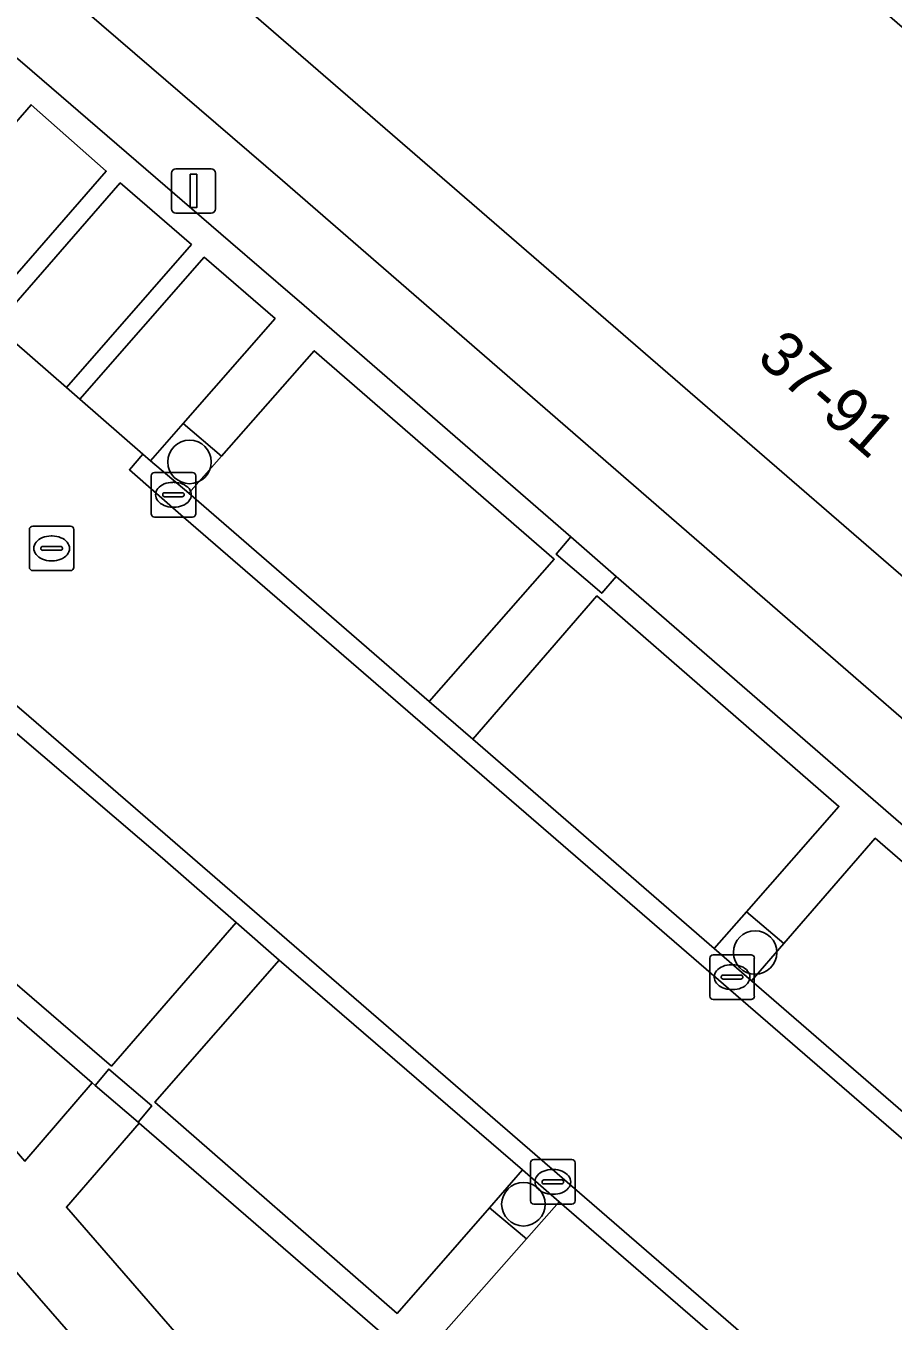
# Model space of a CAD drawing. Extents: x 161881 to 162523, y 381678 to 382381.
# Drawn here: x 162001.95 to 162021.44, y 382171.7 to 382200.83 of the extents above; entities that cross this region are included whole.
import ezdxf

# ---------------------------------------------------------------- set-up
doc = ezdxf.new("R2010")
doc.units = 0
for name, color, linetype in [('IMGEO_Boom', 7, 'Continuous'), ('IMGEO_Erf', 7, 'Continuous'), ('IMGEO_Groenvoorziening', 7, 'Continuous'), ('IMGEO_Kolk', 7, 'Continuous'), ('IMGEO_Lichtmast', 7, 'Continuous'), ('IMGEO_Pand', 7, 'Continuous'), ('IMGEO_Pand_nummerreeks', 7, 'Continuous'), ('IMGEO_Parkeervlak_open', 7, 'Continuous'), ('IMGEO_Rijbaan_lokaal_open', 7, 'Continuous'), ('IMGEO_Rioolput', 7, 'Continuous'), ('IMGEO_Voetpad_op_trap', 7, 'Continuous'), ('IMGEO_Voetpad_open', 7, 'Continuous')]:
    doc.layers.add(name, color=color, linetype=linetype)

msp = doc.modelspace()

# ---------------------------------------------------------------- linework, layer by layer
at = {"layer": 'IMGEO_Boom'}
for centre in [(162005.625, 382191.022), (162018.336, 382179.992), (162013.128, 382174.328)]:
    msp.add_circle(centre, 0.489, dxfattribs=at)
at = {"layer": 'IMGEO_Erf'}
for points in [[(162041.152, 382183.891), (162035.04, 382176.852), (162004.335, 382203.455), (162003.926, 382202.983), (162003.275, 382203.547), (162002.15, 382202.152), (162007.715, 382197.353), (162034.901, 382173.742), (162058.69, 382153.142)], [(162030.201, 382140.112), (161996.66, 382178.627), (161990.016, 382186.254), (161988.587, 382187.894), (161980.177, 382180.625), (161980.188, 382180.574), (161984.998, 382159.715), (161990.302, 382150.73)]]:
    msp.add_lwpolyline(points, dxfattribs=at)
at = {"layer": 'IMGEO_Groenvoorziening'}
for points in [[(162006.341, 382191.151), (162005.484, 382191.889), (162004.744, 382191.044), (162005.61, 382190.321)], [(161997.32, 382182.356), (161993.312, 382185.812), (161993.031, 382185.565), (162001.926, 382175.294), (162003.438, 382177.057)], [(162018.145, 382180.908), (162017.419, 382180.08), (162018.255, 382179.355), (162018.982, 382180.193)], [(162004.491, 382176.151), (162002.856, 382174.263), (162013.07, 382162.502), (162016.152, 382166.051)], [(162013.934, 382174.385), (162013.107, 382175.099), (162012.366, 382174.25), (162013.2, 382173.552)]]:
    msp.add_lwpolyline(points, close=True, dxfattribs=at)
at = {"layer": 'IMGEO_Kolk'}
for p, q in [((162004.763, 382189.858), (162004.763, 382190.71)), ((162004.838, 382190.784), (162005.69, 382190.784)), ((162005.764, 382190.71), (162005.764, 382189.858)), ((162005.251, 382190.564), (162005.276, 382190.564)), ((162005.022, 382190.278), (162005.022, 382190.29)), ((162005.46, 382190.241), (162005.062, 382190.241)), ((162005.065, 382190.327), (162005.463, 382190.327)), ((162005.506, 382190.29), (162005.506, 382190.278)), ((162005.274, 382190.004), (162005.249, 382190.004)), ((162005.69, 382189.784), (162004.838, 382189.784)), ((162017.392, 382179.936), (162018.244, 382179.936)), ((162017.317, 382179.01), (162017.317, 382179.862)), ((162017.805, 382179.716), (162017.83, 382179.716)), ((162018.318, 382179.862), (162018.318, 382179.01)), ((162017.576, 382179.43), (162017.576, 382179.442)), ((162018.014, 382179.393), (162017.616, 382179.393)), ((162017.619, 382179.479), (162018.017, 382179.479)), ((162018.06, 382179.442), (162018.06, 382179.43)), ((162017.828, 382179.156), (162017.803, 382179.156)), ((162018.244, 382178.936), (162017.392, 382178.936)), ((162013.289, 382174.406), (162013.289, 382175.258)), ((162013.364, 382175.332), (162014.216, 382175.332)), ((162014.29, 382175.258), (162014.29, 382174.406)), ((162013.777, 382175.112), (162013.802, 382175.112)), ((162013.548, 382174.826), (162013.548, 382174.838)), ((162013.986, 382174.789), (162013.588, 382174.789)), ((162013.591, 382174.875), (162013.989, 382174.875)), ((162014.032, 382174.838), (162014.032, 382174.826)), ((162013.8, 382174.552), (162013.775, 382174.552)), ((162014.216, 382174.332), (162013.364, 382174.332))]:
    msp.add_line(p, q, dxfattribs=at)
for points in [[(162004.763, 382189.858), (162004.763, 382190.71)], [(162004.838, 382190.784), (162005.69, 382190.784)], [(162005.764, 382190.71), (162005.764, 382189.858)], [(162005.69, 382189.784), (162004.838, 382189.784)], [(162017.392, 382179.936), (162018.244, 382179.936)], [(162017.317, 382179.01), (162017.317, 382179.862)], [(162018.318, 382179.862), (162018.318, 382179.01)], [(162018.244, 382178.936), (162017.392, 382178.936)], [(162013.289, 382174.406), (162013.289, 382175.258)], [(162013.364, 382175.332), (162014.216, 382175.332)], [(162014.29, 382175.258), (162014.29, 382174.406)], [(162014.216, 382174.332), (162013.364, 382174.332)]]:
    msp.add_lwpolyline(points, dxfattribs=at)
for centre, radius, start, end in [((162004.84, 382190.708), 0.0765, 91.552, 178.448), ((162004.84, 382190.708), 0.0765, 91.552, 178.448), ((162005.688, 382190.708), 0.0765, 1.552, 88.448), ((162005.688, 382190.708), 0.0765, 1.552, 88.448), ((162005.062, 382190.287), 0.0403, 85.8775, 175.7526), ((162005.059, 382190.277), 0.0366, 178.938, 274.7102), ((162005.463, 382190.284), 0.043, 264.8664, 352.4533), ((162005.467, 382190.289), 0.0386, 1.7309, 96.639), ((162004.84, 382189.86), 0.0765, 181.552, 268.448), ((162004.84, 382189.86), 0.0765, 181.552, 268.448), ((162005.688, 382189.86), 0.0765, 271.552, 358.448), ((162005.688, 382189.86), 0.0765, 271.552, 358.448), ((162017.394, 382179.86), 0.0765, 91.552, 178.448), ((162017.394, 382179.86), 0.0765, 91.552, 178.448), ((162018.242, 382179.86), 0.0765, 1.552, 88.448), ((162018.242, 382179.86), 0.0765, 1.552, 88.448), ((162017.616, 382179.439), 0.0403, 85.8775, 175.7526), ((162017.613, 382179.429), 0.0366, 178.938, 274.7102), ((162018.017, 382179.436), 0.043, 264.8664, 352.4533), ((162018.021, 382179.441), 0.0386, 1.7309, 96.639), ((162017.394, 382179.012), 0.0765, 181.552, 268.448), ((162017.394, 382179.012), 0.0765, 181.552, 268.448), ((162018.242, 382179.012), 0.0765, 271.552, 358.448), ((162018.242, 382179.012), 0.0765, 271.552, 358.448), ((162013.366, 382175.256), 0.0765, 91.552, 178.448), ((162013.366, 382175.256), 0.0765, 91.552, 178.448), ((162014.214, 382175.256), 0.0765, 1.552, 88.448), ((162014.214, 382175.256), 0.0765, 1.552, 88.448), ((162013.588, 382174.835), 0.0403, 85.8775, 175.7526), ((162013.585, 382174.825), 0.0366, 178.938, 274.7102), ((162013.989, 382174.832), 0.043, 264.8664, 352.4533), ((162013.993, 382174.837), 0.0386, 1.7309, 96.639), ((162013.366, 382174.408), 0.0765, 181.552, 268.448), ((162013.366, 382174.408), 0.0765, 181.552, 268.448), ((162014.214, 382174.408), 0.0765, 271.552, 358.448), ((162014.214, 382174.408), 0.0765, 271.552, 358.448)]:
    msp.add_arc(centre, radius, start, end, dxfattribs=at)
for centre, major_axis, ratio, start_param, end_param in [((162005.25, 382190.284), (-0.387, 0.002), 0.722429, 4.712389, 7.853982), ((162005.275, 382190.284), (-0.39, 0.002), 0.717154, 1.570796, 4.712389), ((162017.804, 382179.436), (-0.387, 0.002), 0.722429, 4.712389, 7.853982), ((162017.829, 382179.436), (-0.39, 0.002), 0.717154, 1.570796, 4.712389), ((162013.776, 382174.832), (-0.387, 0.002), 0.722429, 4.712389, 7.853982), ((162013.801, 382174.832), (-0.39, 0.002), 0.717154, 1.570796, 4.712389)]:
    msp.add_ellipse(centre, major_axis=major_axis, ratio=ratio, start_param=start_param, end_param=end_param, dxfattribs=at)
at = {"layer": 'IMGEO_Lichtmast'}
for p, q in [((162005.218, 382196.717), (162005.218, 382197.517)), ((162005.218, 382197.517), (162005.218, 382196.717)), ((162005.318, 382197.617), (162006.108, 382197.617)), ((162006.108, 382197.617), (162005.318, 382197.617)), ((162006.208, 382197.517), (162006.208, 382196.717)), ((162006.208, 382196.717), (162006.208, 382197.517)), ((162006.108, 382196.617), (162005.318, 382196.617)), ((162005.318, 382196.617), (162006.108, 382196.617))]:
    msp.add_line(p, q, dxfattribs=at)
msp.add_lwpolyline([(162005.638, 382197.492), (162005.788, 382197.492), (162005.788, 382196.742), (162005.638, 382196.742), (162005.638, 382197.492)], dxfattribs=at)
for centre, start, end in [((162005.318, 382197.517), 90, 180), ((162005.318, 382197.517), 90, 180), ((162006.108, 382197.517), 0, 90), ((162006.108, 382197.517), 360, 90), ((162005.318, 382196.717), 180, 270), ((162005.318, 382196.717), 180, 270), ((162006.108, 382196.717), 270, 0), ((162006.108, 382196.717), 270, 0)]:
    msp.add_arc(centre, 0.1, start, end, dxfattribs=at)
at = {"layer": 'IMGEO_Pand'}
msp.add_lwpolyline([(162018.121, 382203.859), (162014.282, 382207.186), (162010.443, 382210.514), (162004.335, 382203.455), (162035.04, 382176.852), (162041.152, 382183.891), (162041.023, 382184.008)], close=True, dxfattribs=at)
at = {"layer": 'IMGEO_Parkeervlak_open'}
for points in [[(162002.065, 382199.055), (161999.247, 382195.812), (162000.943, 382194.34), (162003.754, 382197.564)], [(162004.069, 382197.299), (162001.266, 382194.083), (162002.861, 382192.693), (162005.666, 382195.91)], [(162007.548, 382194.247), (162005.956, 382195.624), (162003.16, 382192.431), (162004.578, 382191.195), (162004.744, 382191.044), (162005.484, 382191.889)], [(162006.341, 382191.151), (162005.61, 382190.321), (162011.011, 382185.637), (162013.82, 382188.833), (162008.429, 382193.522)], [(162011.989, 382184.789), (162017.419, 382180.08), (162018.145, 382180.908), (162020.22, 382183.275), (162014.78, 382188.011)], [(162001.236, 382185.346), (162000.513, 382184.511), (161998.439, 382182.114), (162003.868, 382177.436), (162006.67, 382180.667), (162005.021, 382182.115)], [(162018.982, 382180.193), (162018.255, 382179.355), (162023.729, 382174.608), (162026.506, 382177.825), (162021.034, 382182.559)], [(162007.638, 382179.817), (162004.846, 382176.622), (162010.291, 382171.872), (162012.366, 382174.25), (162013.107, 382175.099)], [(162013.934, 382174.385), (162013.2, 382173.552), (162011.116, 382171.188), (162016.581, 382166.476), (162019.379, 382169.666)]]:
    msp.add_lwpolyline(points, close=True, dxfattribs=at)
at = {"layer": 'IMGEO_Rijbaan_lokaal_open'}
for points in [[(162024.055, 382173.714), (162005.488, 382189.784), (162004.274, 382190.846), (162004.578, 382191.195), (162003.16, 382192.431), (162002.861, 382192.693), (162001.266, 382194.083)], [(162001.899, 382185.403), (162036.967, 382155.028)]]:
    msp.add_lwpolyline(points, dxfattribs=at)
for points in [[(162023.729, 382174.608), (162018.255, 382179.355), (162017.419, 382180.08), (162011.989, 382184.789), (162011.011, 382185.637), (162005.61, 382190.321), (162004.744, 382191.044), (162004.578, 382191.195), (162004.274, 382190.846), (162005.488, 382189.784), (162024.055, 382173.714), (162042.512, 382157.689), (162042.811, 382158.044), (162042.829, 382158.065), (162037.387, 382162.778), (162036.426, 382163.61), (162030.974, 382168.332), (162030.15, 382169.045), (162024.683, 382173.78), (162024.348, 382174.07)], [(162001.899, 382185.403), (162000.705, 382186.422), (162000.438, 382186.65), (162000.135, 382186.301), (162000.395, 382186.065), (162000.428, 382186.035), (162001.236, 382185.346), (162005.021, 382182.115), (162006.67, 382180.667), (162007.638, 382179.817), (162013.107, 382175.099), (162013.934, 382174.385), (162019.379, 382169.666), (162020.364, 382168.811), (162025.835, 382164.089), (162026.682, 382163.354), (162032.109, 382158.646), (162033.054, 382157.803), (162036.646, 382154.691), (162036.967, 382155.028)]]:
    msp.add_lwpolyline(points, close=True, dxfattribs=at)
at = {"layer": 'IMGEO_Rioolput'}
for p, q in [((162002.025, 382188.652), (162002.025, 382189.504)), ((162002.1, 382189.578), (162002.952, 382189.578)), ((162003.026, 382189.504), (162003.026, 382188.652)), ((162002.513, 382189.358), (162002.538, 382189.358)), ((162002.284, 382189.072), (162002.284, 382189.084)), ((162002.722, 382189.035), (162002.324, 382189.035)), ((162002.327, 382189.121), (162002.725, 382189.121)), ((162002.768, 382189.084), (162002.768, 382189.072)), ((162002.536, 382188.798), (162002.511, 382188.798)), ((162002.952, 382188.578), (162002.1, 382188.578))]:
    msp.add_line(p, q, dxfattribs=at)
for points in [[(162002.025, 382188.652), (162002.025, 382189.504)], [(162002.1, 382189.578), (162002.952, 382189.578)], [(162003.026, 382189.504), (162003.026, 382188.652)], [(162002.952, 382188.578), (162002.1, 382188.578)]]:
    msp.add_lwpolyline(points, dxfattribs=at)
for centre, radius, start, end in [((162002.102, 382189.502), 0.0765, 91.552, 178.448), ((162002.102, 382189.502), 0.0765, 91.552, 178.448), ((162002.95, 382189.502), 0.0765, 1.552, 88.448), ((162002.95, 382189.502), 0.0765, 1.552, 88.448), ((162002.324, 382189.081), 0.0403, 85.8775, 175.7526), ((162002.321, 382189.071), 0.0366, 178.938, 274.7102), ((162002.725, 382189.078), 0.043, 264.8664, 352.4533), ((162002.729, 382189.083), 0.0386, 1.7309, 96.639), ((162002.102, 382188.654), 0.0765, 181.552, 268.448), ((162002.102, 382188.654), 0.0765, 181.552, 268.448), ((162002.95, 382188.654), 0.0765, 271.552, 358.448), ((162002.95, 382188.654), 0.0765, 271.552, 358.448)]:
    msp.add_arc(centre, radius, start, end, dxfattribs=at)
for centre, major_axis, ratio, start_param, end_param in [((162002.512, 382189.078), (-0.387, 0.002), 0.722429, 4.712389, 7.853982), ((162002.537, 382189.078), (-0.39, 0.002), 0.717154, 1.570796, 4.712389)]:
    msp.add_ellipse(centre, major_axis=major_axis, ratio=ratio, start_param=start_param, end_param=end_param, dxfattribs=at)
at = {"layer": 'IMGEO_Voetpad_op_trap'}
for points in [[(162014.192, 382189.336), (162013.862, 382188.952), (162014.888, 382188.07), (162015.213, 382188.449)], [(162003.81, 382177.37), (162003.503, 382177.001), (162004.468, 382176.171), (162004.774, 382176.539)]]:
    msp.add_lwpolyline(points, close=True, dxfattribs=at)
at = {"layer": 'IMGEO_Voetpad_open'}
for points in [[(162058.69, 382153.142), (162034.901, 382173.742), (162007.715, 382197.353), (162002.15, 382202.152), (162001.003, 382200.728), (162001.87, 382200.001), (162006.547, 382195.968), (162007.937, 382194.769), (162008.089, 382194.637), (162014.192, 382189.336), (162015.213, 382188.449), (162026.877, 382178.317), (162027.903, 382177.426), (162030.56, 382175.118), (162039.593, 382167.298)], [(162026.877, 382178.317), (162015.213, 382188.449), (162014.888, 382188.07), (162013.862, 382188.952), (162014.192, 382189.336), (162008.089, 382194.637), (162007.937, 382194.769), (162006.547, 382195.968), (162001.87, 382200.001)], [(161999.247, 382195.812), (162002.065, 382199.055), (162003.754, 382197.564), (162000.943, 382194.34)], [(162001.266, 382194.083), (162004.069, 382197.299), (162005.666, 382195.91), (162002.861, 382192.693), (162003.16, 382192.431), (162005.956, 382195.624), (162007.548, 382194.247), (162005.484, 382191.889), (162006.341, 382191.151), (162008.429, 382193.522), (162013.82, 382188.833), (162011.011, 382185.637), (162011.989, 382184.789), (162014.78, 382188.011), (162020.22, 382183.275), (162018.145, 382180.908), (162018.982, 382180.193), (162021.034, 382182.559), (162026.506, 382177.825)], [(162025.152, 382148.644), (162029.896, 382154.126), (162029.88, 382154.141), (162028.872, 382155.015), (162028.853, 382155.032), (162024.17, 382149.745), (162014.005, 382161.432), (162017.138, 382165.198), (162016.175, 382166.031), (162016.152, 382166.051), (162013.07, 382162.502), (162002.856, 382174.263), (162004.491, 382176.151), (162004.468, 382176.171), (162003.503, 382177.001), (162003.438, 382177.057), (162001.926, 382175.294), (161993.031, 382185.565), (161993.312, 382185.812), (161991.197, 382187.619), (161990.016, 382186.254), (161996.66, 382178.627), (162030.201, 382140.112)], [(161997.32, 382182.356), (162003.438, 382177.057), (162003.503, 382177.001), (162003.81, 382177.37), (162004.774, 382176.539), (162004.468, 382176.171), (162004.491, 382176.151), (162016.152, 382166.051)], [(162011.116, 382171.188), (162013.2, 382173.552), (162012.366, 382174.25), (162010.291, 382171.872), (162004.846, 382176.622), (162007.638, 382179.817), (162006.67, 382180.667), (162003.868, 382177.436), (161998.439, 382182.114)]]:
    msp.add_lwpolyline(points, dxfattribs=at)

# ---------------------------------------------------------------- texts
at = {"layer": 'IMGEO_Pand_nummerreeks'}
msp.add_text('37-91', height=1, rotation=318.896, dxfattribs=at).set_placement((162018.343, 382193.313))

doc.saveas('drawing.dxf')
